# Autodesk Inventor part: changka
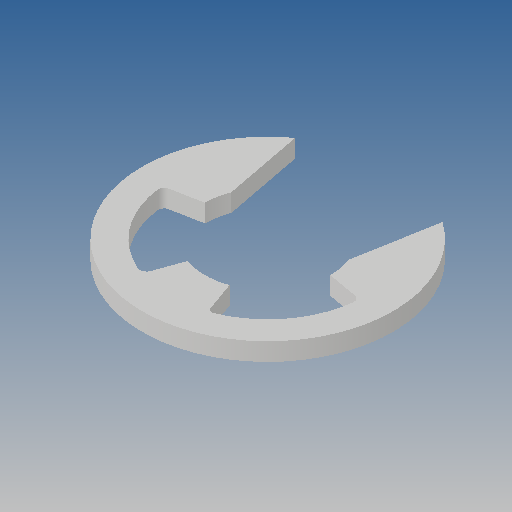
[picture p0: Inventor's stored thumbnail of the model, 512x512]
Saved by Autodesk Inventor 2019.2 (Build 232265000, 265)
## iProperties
Created: 2013-07
Part Number: changka
Material: Ogólny
Document SubType Name: Modeling
Designer: CADENGINEERING4
Density: 1 g/cm^3
Appearance: Domyślna
Author: CADENGINEERING4
Revision Number: ÈÎºÎ
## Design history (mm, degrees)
feature "CALC50KH-5-solid1"
node "Bryła1"
